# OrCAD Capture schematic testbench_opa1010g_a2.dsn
size A
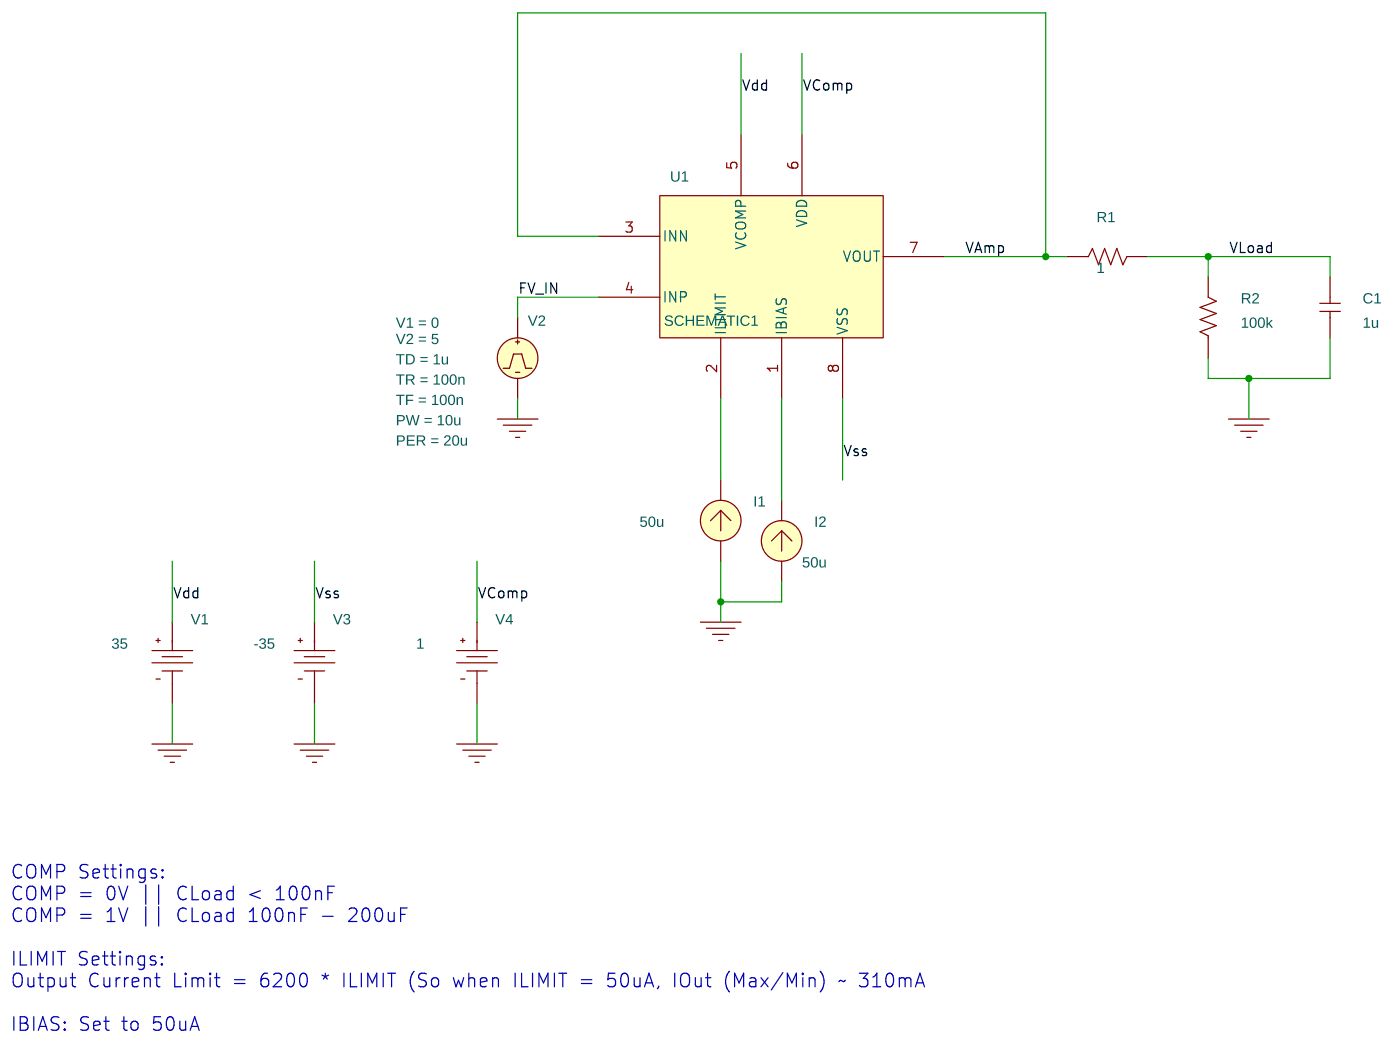
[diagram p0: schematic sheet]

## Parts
C1  1u  [cap196]
I1  IDC
I2  IDC
R1  1  [AXRC05]
R2  100k  [AXRC05]
U1  SCHEMATIC1
V1  VDC
V2  VPULSE
V3  VDC
V4  VDC

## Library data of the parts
C1 = C
I1 I2 = IDC: DC: 50u
R1 R2 = R
U1 = SCHEMATIC1
V1 = VDC: DC: 35
V2 = VPULSE: PER: 20u; PW: 10u; TD: 1u; TF: 100n; TR: 100n; V1: 0; V2: 5
V3 = VDC: DC: -35
V4 = VDC: DC: 1

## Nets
Vdd: U1.5(VCOMP) V1.0(+)
Vss: U1.8(VSS) V3.0(+)
0: C1.1 I1.1(+) I2.1(+) R2.1 V1.1(-) V2.2(-) V3.1(-) V4.1(-)
FV_IN: U1.4(INP) V2.1(+)
VAmp: R1.1 U1.3(INN) U1.7(VOUT)
VComp: U1.6(VDD) V4.0(+)
VLoad: C1.2 R1.2 R2.2
N00391: I1.2(-) U1.2(ILIMIT)
N00395: I2.2(-) U1.1(IBIAS)

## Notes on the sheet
- COMP Settings:
  COMP = 0V || CLoad < 100nF
  COMP = 1V || CLoad 100nF - 200uF
  ILIMIT Settings:
  Output Current Limit = 6200 * ILIMIT (So when ILIMIT = 50uA, IOut (Max/Min) ~ 310mA
  IBIAS: Set to 50uA
